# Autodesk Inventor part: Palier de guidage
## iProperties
Author: Flavien MARTY
Shininess: 27.0
PropertySet Name: _Private Model Information
Created: 2001-10
Part Number: Palier de guidage
Material: Par défaut
Document SubType Name: Modélisation
Designer: Flavien MARTY
Control State: 0
Master: False
Checked Out: False
PropertySet Name: Design Tracking Control
Density: 0.0
Volumn: 0.0
Area: 0.0
PropertySet Name: Model Information
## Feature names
1. Base1
